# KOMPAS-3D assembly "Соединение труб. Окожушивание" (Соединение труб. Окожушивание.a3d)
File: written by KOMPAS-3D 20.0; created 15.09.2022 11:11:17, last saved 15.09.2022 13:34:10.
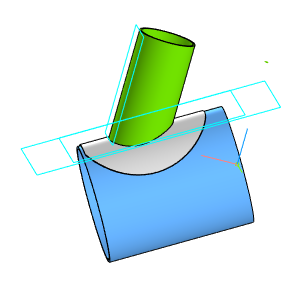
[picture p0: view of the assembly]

Document properties: Полное имя файла: D:\YAKOVLEV\ПРОЕКТЫ\ДЦ-2. ДП-7 Газопровод Окожушивание\ПРОБА Соединение труб. Окожушивание\Соединение труб. Окожушивание.a3d

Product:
- Part/product: Соединение труб. Окожушивание
    Масса: 6196.61
  - Component [assembly]: Соединение труб  | Масса: 5745.48; source file: Соединение труб.a3d
  - Component [detail]: Кожух 1 (трубы)  | Материал: Сталь 45  ГОСТ 1050-2013 (density 7810 kg/m3); Масса: 451.123; source file: Кожух 1 (трубы).m3d

Referenced files in D:\YAKOVLEV\ПРОЕКТЫ\ДЦ-2. ДП-7 Газопровод Окожушивание\ПРОБА Соединение труб. Окожушивание\: Соединение труб.a3d, Кожух 1 (трубы).m3d
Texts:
  Точка начала. Х
  Точка начала. Y
  Точка начала. Z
